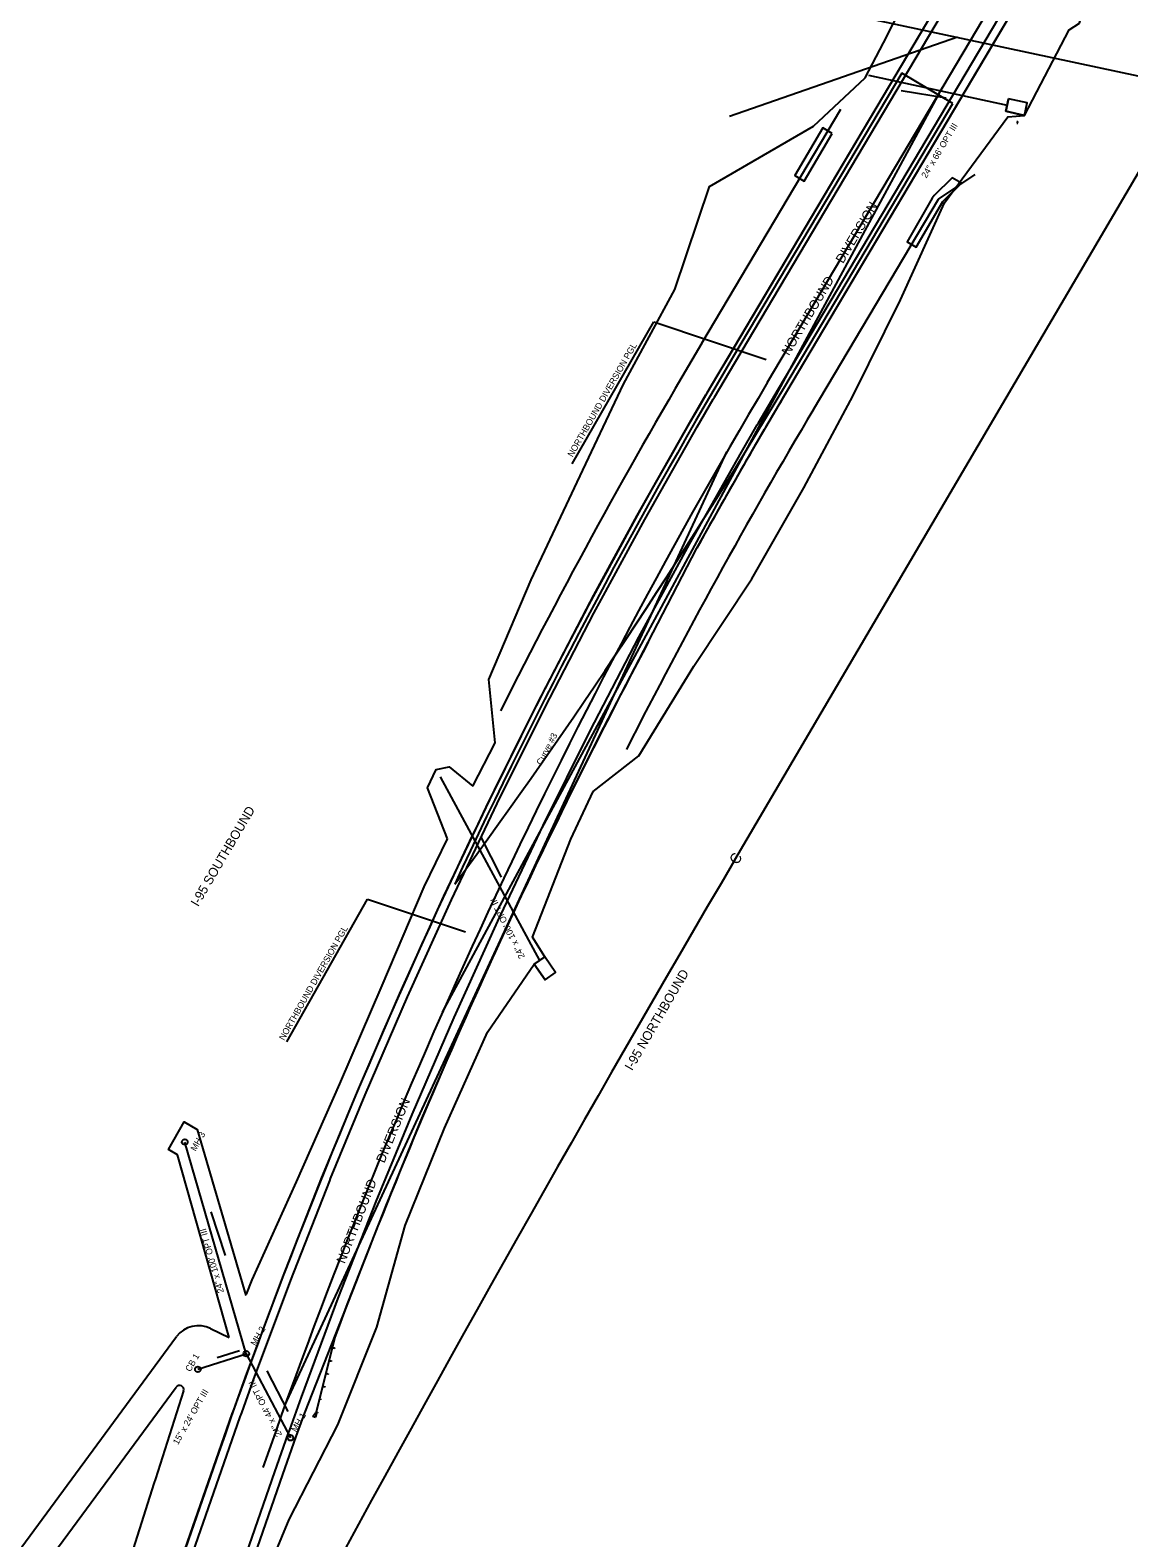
# Model space of a CAD drawing. Extents: x 1160458 to 1162290, y 615427 to 618737.
# Drawn here: x 1160878 to 1161395, y 616580 to 617290 of the extents above; entities that cross this region are included whole.
import ezdxf

# ---------------------------------------------------------------- set-up
doc = ezdxf.new("R2010")
doc.units = 0
for name, color, linetype in [('1', 7, 'Continuous'), ('_55 MPH DETOUR PVM SHARED', 7, 'Continuous'), ('_Station Equation', 7, 'Continuous'), ('ANNOTATION', 7, 'Continuous'), ('D_Drainage_Culvert', 7, 'Continuous'), ('D_Drainage_Ditch_Line', 7, 'Continuous'), ('D_Drainage_MH', 7, 'Continuous'), ('D_Drainage_RipRap', 7, 'Continuous'), ('D_Drainage_Text', 7, 'Continuous'), ('D_Guardrail_Beam_Lt', 7, 'Continuous'), ('D_Guardrail_End_MELT', 7, 'Continuous'), ('D_Roadway_Centerline', 7, 'Continuous'), ('D_Roadway_Edge_Pavement', 7, 'Continuous'), ('D_Roadway_Edge_TW', 7, 'Continuous'), ('D_Slope_Cut', 7, 'Continuous'), ('D_Slope_Fill', 7, 'Continuous'), ('D_Text_Standard', 7, 'Continuous'), ('P_Driveway_Hatch', 7, 'Continuous'), ('S_Ground_SpotElevation', 7, 'Continuous')]:
    doc.layers.add(name, color=color, linetype=linetype)

msp = doc.modelspace()

# ---------------------------------------------------------------- linework, layer by layer
at = {"layer": '1'}
msp.add_line((1161209.81, 616899.51), (1162286.6, 618733.81), dxfattribs=at)
msp.add_arc((1171291.23, 610981.4), 11690.13, 149.585749, 157.64029, dxfattribs=at)
at = {"layer": '_55 MPH DETOUR PVM SHARED'}
for p, q in [((1161288.42, 617270.01), (1161209.24, 617136.68)), ((1161312.5, 617255.72), (1161288.42, 617270.01)), ((1161233.31, 617122.38), (1161312.5, 617255.72))]:
    msp.add_line(p, q, dxfattribs=at)
for centre, start, end in [((1163637.32, 615694.67), 149.29443, 155.00197), ((1158805.23, 618564.39), 323.58689, 329.29443)]:
    msp.add_arc(centre, 2824, start, end, dxfattribs=at)
at = {"layer": '_Station Equation'}
msp.add_line((1161314.69, 617286.83), (1161207.36, 617249.56), dxfattribs=at)
at = {"layer": 'D_Drainage_Culvert'}
for p, q in [((1161272.71, 617269.05), (1161338.01, 617254.9)), ((1161070.99, 616938.57), (1161117.86, 616852.07)), ((1160979.75, 616666.95), (1160950.78, 616766.62)), ((1160956.94, 616659.61), (1160979.75, 616666.95)), ((1160979.75, 616666.95), (1161000.54, 616627.36))]:
    msp.add_line(p, q, dxfattribs=at)
at = {"layer": 'D_Drainage_Ditch_Line'}
for p, q in [((1161305.63, 617210.66), (1161322.98, 617222.18)), ((1161246.79, 617111.58), (1161305.63, 617210.66)), ((1160865.58, 616541.07), (1160946.69, 616651.23))]:
    msp.add_line(p, q, dxfattribs=at)
msp.add_lwpolyline([(1160950.21, 616649.43), (1160936.96, 616608.03), (1160936.24, 616605.79), (1160907.92, 616516.58), (1160907.66, 616515.75), (1160907.4, 616514.93), (1160907.13, 616514.12), (1160906.87, 616513.29), (1160904.13, 616504.89), (1160903.65, 616503.46), (1160903.18, 616502.05), (1160902.69, 616500.64), (1160902.19, 616499.21), (1160900.09, 616493.32), (1160899.57, 616491.83), (1160899.04, 616490.35), (1160898.51, 616488.87), (1160897.99, 616487.38), (1160884.4, 616448.95)], dxfattribs=at)
msp.add_arc((1160948.3, 616650.04), 2, 342.24986, 143.63328, dxfattribs=at)
at = {"layer": 'D_Drainage_MH'}
for centre in [(1160950.78, 616766.62), (1160979.75, 616666.95), (1160956.94, 616659.61), (1161000.54, 616627.36)]:
    msp.add_circle(centre, 1.33, dxfattribs=at)
at = {"layer": 'D_Drainage_RipRap'}
for p, q in [((1161337.37, 617251.97), (1161338.64, 617257.83)), ((1161347.44, 617255.92), (1161338.64, 617257.83)), ((1161346.17, 617250.06), (1161337.37, 617251.97)), ((1161346.17, 617250.06), (1161347.44, 617255.92)), ((1161115.32, 616850.38), (1161120.26, 616853.78)), ((1161125.37, 616846.38), (1161120.26, 616853.78)), ((1161120.44, 616842.97), (1161115.32, 616850.38)), ((1161120.44, 616842.97), (1161125.37, 616846.38))]:
    msp.add_line(p, q, dxfattribs=at)
for points in [[(1161338.64, 617257.83), (1161337.37, 617251.97), (1161346.17, 617250.06), (1161347.44, 617255.92)], [(1161255.6, 617241.59), (1161251.29, 617244.13), (1161238.07, 617221.68), (1161242.38, 617219.15)], [(1161316.47, 617218.09), (1161312.12, 617220.67), (1161303.62, 617212.31), (1161302.78, 617211), (1161290.92, 617190.54), (1161295.24, 617188.02), (1161307.73, 617209.44)], [(1161120.26, 616853.78), (1161115.32, 616850.38), (1161120.44, 616842.97), (1161125.37, 616846.38)]]:
    msp.add_lwpolyline(points, close=True, dxfattribs=at)
at = {"layer": 'D_Guardrail_Beam_Lt'}
for p, q in [((1161395.02, 617453.42), (1161206.29, 617135.63)), ((1161233.79, 617119.3), (1161422.52, 617437.09)), ((1161169.04, 617002.03), (1161191.85, 617046.2)), ((1160966.79, 616620.56), (1160922.58, 616493.37))]:
    msp.add_line(p, q, dxfattribs=at)
for radius, start, end in [(2826, 149.29443, 160.83052), (2794.02, 149.29443, 151.02281), (2793.02, 152.04231, 159.41137)]:
    msp.add_arc((1163636.09, 615692.6), radius, start, end, dxfattribs=at)
at = {"layer": 'D_Guardrail_End_MELT'}
for p, q in [((1161021.74, 616675.89), (1161012.68, 616639.5)), ((1161020.23, 616669.82), (1161020.72, 616669.7)), ((1161020.78, 616669.95), (1161020.66, 616669.46)), ((1161020.72, 616669.7), (1161021.2, 616669.58)), ((1161021.26, 616669.82), (1161021.14, 616669.34)), ((1161018.72, 616663.76), (1161019.21, 616663.64)), ((1161019.27, 616663.88), (1161019.15, 616663.39)), ((1161019.21, 616663.64), (1161019.69, 616663.52)), ((1161019.75, 616663.76), (1161019.63, 616663.27)), ((1161017.21, 616657.69), (1161017.7, 616657.57)), ((1161017.76, 616657.82), (1161017.64, 616657.33)), ((1161017.7, 616657.57), (1161018.18, 616657.45)), ((1161018.24, 616657.69), (1161018.12, 616657.21)), ((1161015.7, 616651.63), (1161016.19, 616651.51)), ((1161016.25, 616651.75), (1161016.13, 616651.27)), ((1161016.19, 616651.51), (1161016.67, 616651.39)), ((1161016.73, 616651.63), (1161016.61, 616651.14)), ((1161011.31, 616637.87), (1161012.32, 616639.07)), ((1161012.8, 616638.95), (1161012.31, 616636.97)), ((1161012.32, 616639.07), (1161012.8, 616638.95)), ((1161012.68, 616639.5), (1161012.56, 616639.01)), ((1161012.68, 616639.5), (1161013.17, 616639.38)), ((1161013.23, 616639.62), (1161013.11, 616639.14)), ((1161014.19, 616645.56), (1161014.68, 616645.44)), ((1161014.74, 616645.69), (1161014.62, 616645.2)), ((1161011.14, 616637.4), (1161011.31, 616637.87)), ((1161012.31, 616636.97), (1161011.14, 616637.4))]:
    msp.add_line(p, q, dxfattribs=at)
at = {"layer": 'D_Roadway_Centerline'}
for p, q in [((1160573.57, 617445.06), (1162040.51, 617131.87)), ((1161194.25, 617142.78), (1161259.73, 617253.02))]:
    msp.add_line(p, q, dxfattribs=at)
for radius, end in [(2840, 153.27726), (2778.9, 153.06181)]:
    msp.add_arc((1163636.09, 615692.6), radius, 149.29443, end, dxfattribs=at)
at = {"layer": 'D_Roadway_Edge_Pavement'}
for p, q in [((1161169.04, 617002.03), (1161191.91, 617046.31)), ((1161007.3, 616639.13), (1161025.47, 616685.39))]:
    msp.add_line(p, q, dxfattribs=at)
for points in [[(1161191.85, 617046.2), (1161216.32, 617089.48), (1161223.81, 617102.37), (1161224.32, 617103.23), (1161233.79, 617119.31), (1161422.51, 617437.08), (1161432.54, 617453.83), (1161433.05, 617454.68), (1161446, 617475.9), (1161472.45, 617517.99), (1161499.64, 617559.61), (1161499.65, 617559.62)], [(1160922.59, 616493.37), (1160966.8, 616620.56), (1160973.14, 616638.59), (1160973.82, 616640.49), (1160979.37, 616655.94), (1160996.93, 616703.06), (1161015.33, 616749.86), (1161015.77, 616750.95), (1161032.07, 616790.46), (1161052.02, 616836.61), (1161072.78, 616882.41), (1161094.36, 616927.83), (1161116.74, 616972.86), (1161139.91, 617017.48), (1161143.46, 617024.14), (1161163.88, 617061.68), (1161188.63, 617105.45), (1161196.21, 617118.5), (1161196.72, 617119.37), (1161206.3, 617135.62), (1161395.03, 617453.42)], [(1161025.52, 616685.37), (1161027.72, 616691.27), (1161045.9, 616737.52), (1161046.33, 616738.59), (1161062.45, 616777.65), (1161082.16, 616823.27), (1161102.69, 616868.53), (1161124.01, 616913.42), (1161146.13, 616957.93), (1161169.04, 617002.03)], [(1160931.52, 616423.31), (1160941.33, 616450.36), (1160943.46, 616456.34), (1160948.03, 616469.28), (1160952.78, 616482.87), (1160997, 616610.06), (1161003.26, 616627.89), (1161003.93, 616629.76), (1161007.3, 616639.13)]]:
    msp.add_lwpolyline(points, dxfattribs=at)
at = {"layer": 'D_Roadway_Edge_TW'}
for points in [[(1160926.36, 616492.06), (1160970.57, 616619.24), (1160976.9, 616637.26), (1160977.57, 616639.14), (1160983.11, 616654.57), (1161000.65, 616701.63), (1161019.03, 616748.38), (1161019.46, 616749.44), (1161035.75, 616788.9), (1161055.67, 616835), (1161076.4, 616880.73), (1161097.94, 616926.09), (1161120.29, 616971.05), (1161143.45, 617015.63), (1161146.97, 617022.25), (1161167.37, 617059.75), (1161192.1, 617103.47), (1161199.66, 617116.49), (1161200.16, 617117.35), (1161209.73, 617133.6), (1161398.46, 617451.37)], [(1160949.03, 616484.18), (1160993.24, 616611.37), (1160999.51, 616629.22), (1161000.18, 616631.1), (1161005.68, 616646.41), (1161023.07, 616693.05), (1161041.27, 616739.37), (1161041.72, 616740.48), (1161057.86, 616779.59), (1161077.61, 616825.28), (1161098.17, 616870.63), (1161119.53, 616915.6), (1161141.69, 616960.18), (1161164.63, 617004.35), (1161168.15, 617010.96), (1161188.37, 617048.13), (1161212.87, 617091.45), (1161220.37, 617104.38), (1161220.88, 617105.24), (1161230.36, 617121.33), (1161419.1, 617439.13)]]:
    msp.add_lwpolyline(points, dxfattribs=at)
at = {"layer": 'D_Slope_Cut'}
msp.add_line((1160962.92, 616678.81), (1160971.69, 616674.58), dxfattribs=at)
for points in [[(1161097.01, 616954.6), (1161093.9, 616984.47), (1161113.86, 617031.31), (1161135.56, 617077.37), (1161157.29, 617123.55), (1161181.56, 617168.04), (1161197.82, 617216.54), (1161246.79, 617244.96)], [(1161143.14, 616931.66), (1161164.57, 616948.55), (1161190.49, 616990.64), (1161217.82, 617031.82), (1161242.24, 617074.66), (1161265.51, 617118.18), (1161287.75, 617163.13), (1161308.53, 617208.94)], [(1161074.47, 616909.44), (1161065.13, 616933.47), (1161069.21, 616941.98), (1161075.28, 616943.31), (1161086.48, 616934.2)], [(1160971.69, 616674.58), (1160947.41, 616760.57), (1160943.07, 616763.06), (1160950.54, 616776.07), (1160956.61, 616772.59), (1160979.51, 616694.42)], [(1160827, 616511.63), (1160855.92, 616551.61), (1160946.84, 616675.03)]]:
    msp.add_lwpolyline(points, dxfattribs=at)
msp.add_arc((1160957.18, 616667.15), 13, 63.78953, 142.70166, dxfattribs=at)
at = {"layer": 'D_Slope_Fill'}
for points in [[(1161246.79, 617244.96), (1161271.11, 617267.77), (1161279.77, 617284.18), (1161302.44, 617328.86), (1161333.99, 617368.28), (1161357.23, 617412.63), (1161382.77, 617455.61), (1161406.02, 617500.54), (1161430.73, 617544.75), (1161454.64, 617589.61), (1161480.07, 617633.64), (1161482.9, 617636.64)], [(1161308.53, 617208.94), (1161338.28, 617249.42), (1161346.17, 617250.06), (1161367.25, 617290.37), (1161372.03, 617293.55), (1161384.4, 617338.34), (1161407.67, 617382.67), (1161434.38, 617424.96), (1161466.71, 617453.8), (1161468.72, 617457.3)], [(1161086.48, 616934.2), (1161097.01, 616954.6)], [(1160946.97, 616466.26), (1160980.7, 616542.71), (1160999.92, 616588.93), (1161022.85, 616633.52), (1161041.25, 616679.39), (1161054.56, 616727.27), (1161073.15, 616773.14), (1161093.34, 616818.32), (1161115.32, 616850.38), (1161120.44, 616842.97), (1161125.37, 616846.38), (1161120.26, 616853.78), (1161114.5, 616863.05), (1161132.51, 616909.29), (1161143.14, 616931.66)], [(1160979.8, 616694.95), (1160982.5, 616701.73), (1161003.31, 616747.81), (1161023.71, 616793.98), (1161043.75, 616840.27), (1161063.5, 616886.72), (1161074.47, 616909.44)]]:
    msp.add_lwpolyline(points, dxfattribs=at)
at = {"layer": 'D_Text_Standard'}
for p, q in [((1161288.1, 617261.83), (1161309.38, 617258.25)), ((1161133.18, 617085.97), (1161171.58, 617152.92)), ((1161171.58, 617152.92), (1161224.61, 617135.15)), ((1161089.99, 616910.54), (1161099.8, 616891.31)), ((1160998.77, 616813.8), (1161036.85, 616880.93)), ((1161036.85, 616880.93), (1161082.9, 616865.59)), ((1160963, 616733.72), (1160969.86, 616713.26)), ((1160965.98, 616665.15), (1160976.56, 616668.43)), ((1160989.39, 616658.86), (1160999.25, 616639.66))]:
    msp.add_line(p, q, dxfattribs=at)
at = {"layer": 'P_Driveway_Hatch'}
for p, q in [((1161225.21, 617124.4), (1161413.94, 617442.18)), ((1161072.12, 616827.71), (1161307.59, 617263.12)), ((1160997.89, 616642.5), (1161206.04, 617091.62))]:
    msp.add_line(p, q, dxfattribs=at)
msp.add_arc((1163636.09, 615692.6), 2804, 149.29443, 160.83052, dxfattribs=at)
at = {"layer": 'S_Ground_SpotElevation'}
for p, q in [((1161342.53, 617247.15), (1161343.06, 617247.15)), ((1161343.06, 617247.15), (1161342.53, 617246.36)), ((1161342.53, 617246.36), (1161343.05, 617246.36)), ((1161342.63, 617246.75), (1161342.95, 617246.75))]:
    msp.add_line(p, q, dxfattribs=at)

# ---------------------------------------------------------------- texts
msp.add_text('C', height=5, rotation=59.58575).set_placement((1161211.14, 616896.83))
at = {"layer": 'ANNOTATION'}
msp.add_text('Curve #3', height=3, rotation=62.2868, dxfattribs=at).set_placement((1161118.8, 616943.81))
at = {"layer": 'D_Drainage_Text'}
for s, rotation, p in [('24" x 66\' OPT III', 59.17938, (1161299.96, 617220.24)), ('24" x 100\' OPT III', 116.30348, (1161111.02, 616853.87)), ('MH 3', 60.1613, (1160955.87, 616762.04)), ('24" x 100\' OPT III', 105.81654, (1160969.24, 616695.98)), ('MH 2', 60.1613, (1160984.15, 616670.37)), ('CB 1', 60.1613, (1160953.38, 616658.18)), ('24" x 44\' OPT III', 117.14091, (1160996.65, 616628.79)), ('15" x 24\' OPT III', 60.1613, (1160947.56, 616623.82)), ('MH 1', 60.1613, (1161003.26, 616629.78))]:
    msp.add_text(s, height=3, rotation=rotation, dxfattribs=at).set_placement(p)
at = {"layer": 'D_Text_Standard'}
for s, height, rotation, p in [('DIVERSION', 4.375, 59.19909, (1161260.74, 617179.99)), ('NORTHBOUND', 4.375, 59.29956, (1161235.28, 617136.65)), ('NORTHBOUND DIVERSION PGL', 3, 60.1613, (1161133.43, 617088.91)), ('I-95 SOUTHBOUND', 4.375, 59.61298, (1160957.06, 616877.15)), ('NORTHBOUND DIVERSION PGL', 3, 60.4348, (1160997.57, 616814.21)), ('I-95 NORTHBOUND', 4.375, 59.84853, (1161161.4, 616799.92)), ('DIVERSION', 4.375, 67.63708, (1161044.74, 616756.42)), ('NORTHBOUND', 4.375, 68.7949, (1161026.09, 616709.06))]:
    msp.add_text(s, height=height, rotation=rotation, dxfattribs=at).set_placement(p)

doc.saveas('drawing.dxf')
